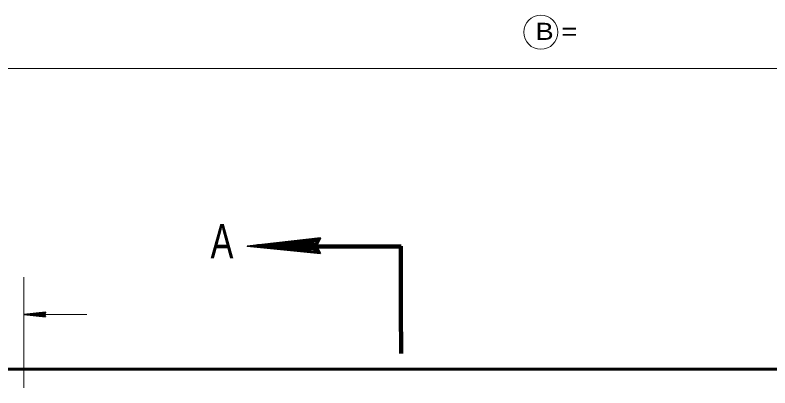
# Model space of a CAD drawing. Extents: x 6.34 to 9.53, y -1.46 to 0.53.
# Drawn here: x 6.7323 to 7.1006, y -0.3987 to -0.2169 of the extents above; entities that cross this region are included whole.
import ezdxf

# ---------------------------------------------------------------- set-up
doc = ezdxf.new("R2010")
doc.units = 0
doc.header["$LTSCALE"] = 0.0033
doc.layers.add('1', color=7, linetype='Continuous', lineweight=40)

msp = doc.modelspace()

# ---------------------------------------------------------------- linework, layer by layer
at = {"layer": '1', "lineweight": 35}
for p, q in [((6.8805, -0.325833), (6.85575, -0.328583)), ((6.8805, -0.326333), (6.85575, -0.329)), ((6.8805, -0.32675), (6.85575, -0.329583)), ((6.88075, -0.327333), (6.855833, -0.32975)), ((6.88125, -0.329583), (6.845583, -0.329583)), ((6.8805, -0.332333), (6.853917, -0.329)), ((6.8805, -0.332333), (6.853917, -0.329583)), ((6.8805, -0.333), (6.853917, -0.32975)), ((6.8805, -0.333), (6.853917, -0.32975)), ((6.8805, -0.332583), (6.853917, -0.32975)), ((6.747167, -0.362917), (6.736583, -0.362917)), ((6.746917, -0.36375), (6.739083, -0.36275)), ((6.746917, -0.36375), (6.739083, -0.362917)), ((6.746917, -0.363917), (6.739083, -0.363)), ((6.746917, -0.363917), (6.739083, -0.363)), ((6.746917, -0.363833), (6.739083, -0.363)), ((6.746917, -0.361833), (6.739583, -0.362667)), ((6.746917, -0.362), (6.739583, -0.36275)), ((6.746917, -0.362083), (6.739583, -0.362917)), ((6.747, -0.36225), (6.739667, -0.363))]:
    msp.add_line(p, q, dxfattribs=at)
at = {"layer": '1', "lineweight": 90}
for p, q in [((6.879083, -0.329667), (6.92075, -0.329667)), ((6.920583, -0.329583), (6.920583, -0.37125)), ((6.92075, -0.371333), (6.92075, -0.381833))]:
    msp.add_line(p, q, dxfattribs=at)
at = {"layer": '1', "lineweight": 13}
for p, q in [((6.736583, -0.398667), (6.736583, -0.34475)), ((6.7465, -0.362917), (6.767333, -0.362917))]:
    msp.add_line(p, q, dxfattribs=at)
at = {"layer": '1', "lineweight": 60}
for p, q in [((6.718917, -0.389583), (6.996917, -0.389583)), ((6.962167, -0.389583), (7.30225, -0.389583))]:
    msp.add_line(p, q, dxfattribs=at)
at = {"layer": '1', "lineweight": 13}
msp.add_lwpolyline([(6.71825, -0.242917), (7.021083, -0.242917), (7.301583, -0.242917)], dxfattribs=at)
at = {"layer": '1', "lineweight": 35}
for points in [[(6.88125, -0.333083), (6.845583, -0.329583), (6.88125, -0.325583), (6.879333, -0.329583)], [(6.878833, -0.32975), (6.863, -0.330083), (6.863, -0.32975), (6.866, -0.32975), (6.878833, -0.330083), (6.868583, -0.330333), (6.879333, -0.33075), (6.871583, -0.330833), (6.879333, -0.33125), (6.8675, -0.330333), (6.851667, -0.32975), (6.85475, -0.329), (6.850583, -0.329), (6.878833, -0.329), (6.8705, -0.3285), (6.879333, -0.3285), (6.861333, -0.32975), (6.879333, -0.3275)], [(6.747167, -0.364), (6.736583, -0.362917), (6.747167, -0.36175), (6.746583, -0.362917)], [(6.746417, -0.363), (6.74175, -0.363083), (6.74175, -0.363), (6.742667, -0.363), (6.746417, -0.363083), (6.743417, -0.363167), (6.746583, -0.36325), (6.744333, -0.363333), (6.746583, -0.363417), (6.743083, -0.363167), (6.738417, -0.363), (6.739333, -0.36275), (6.738083, -0.36275), (6.746417, -0.36275), (6.744, -0.362583), (6.746583, -0.362583), (6.74125, -0.363), (6.746583, -0.362333)]]:
    msp.add_lwpolyline(points, close=True, dxfattribs=at)
for points in [[(6.878833, -0.32975), (6.880083, -0.332333), (6.879333, -0.3315), (6.878833, -0.330333), (6.877833, -0.33075), (6.8785, -0.331833), (6.879, -0.32925), (6.879583, -0.3275), (6.8805, -0.32625)], [(6.746417, -0.363), (6.746833, -0.36375), (6.746583, -0.3635), (6.746417, -0.363167), (6.746167, -0.36325), (6.746333, -0.363583), (6.7465, -0.362833), (6.746667, -0.362333), (6.746917, -0.361917)]]:
    msp.add_lwpolyline(points, dxfattribs=at)
at = {"layer": '1', "lineweight": 13}
msp.add_circle((6.988833, -0.22525), 0.008333, dxfattribs=at)

# ---------------------------------------------------------------- texts
at = {"layer": '1'}
for s, height, width, p in [('B =      ', 0.008334, 1.2, (6.986167, -0.229)), ('A', 0.01667, 0.75, (6.827667, -0.3355))]:
    msp.add_text(s, height=height, dxfattribs=dict(at, width=width)).set_placement(p)

doc.saveas('drawing.dxf')
